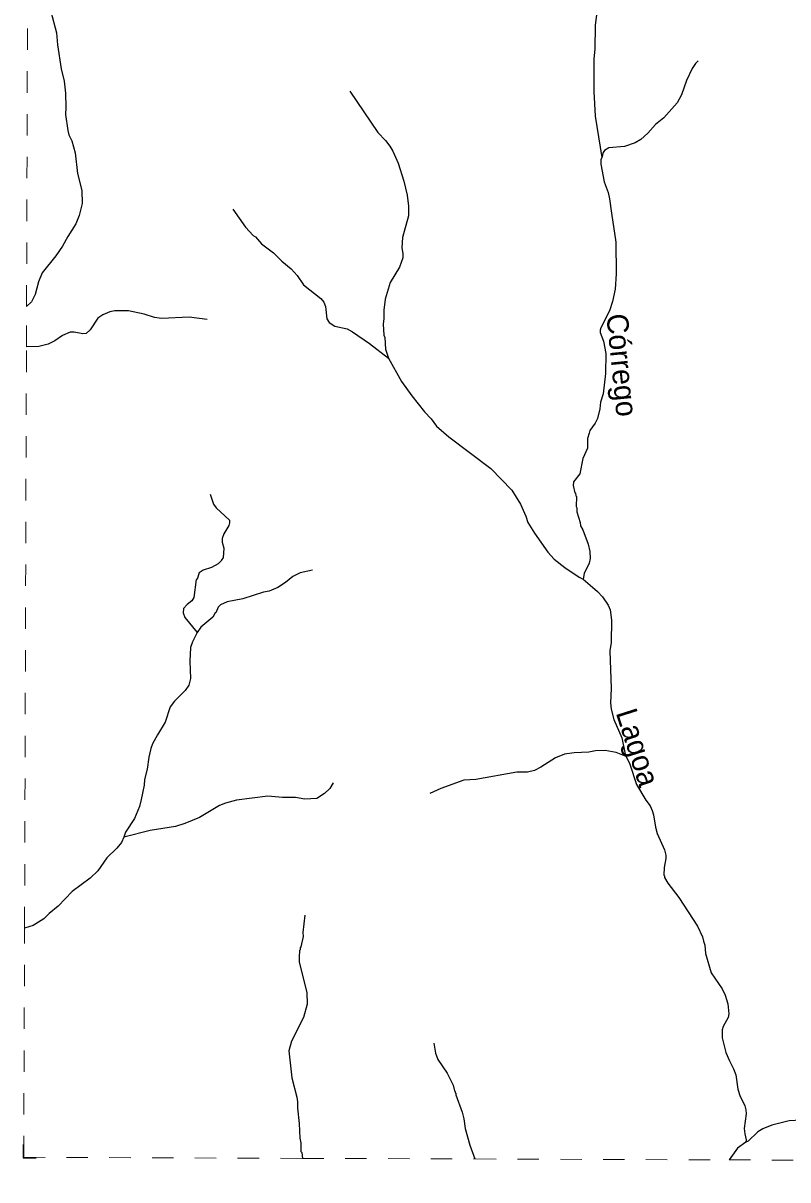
# Model space of a CAD drawing. Extents: x 551.6 to 577.6, y 7567 to 7594.7.
# Drawn here: x 551.61 to 555.19, y 7566.95 to 7572.36 of the extents above; entities that cross this region are included whole.
import ezdxf
from ezdxf.enums import TextEntityAlignment as Align

# ---------------------------------------------------------------- set-up
doc = ezdxf.new("R2010")
doc.units = 0
doc.header["$LTSCALE"] = 0.04
doc.linetypes.add('SHORT_DASHED', pattern=[2.7, 1.5, -1.2])
for name, color, linetype, lineweight in [('53', 7, 'SHORT_DASHED', 13), ('63', 7, 'Continuous', 25), ('7', 7, 'Continuous', 25)]:
    doc.layers.add(name, color=color, linetype=linetype, lineweight=lineweight)
doc.layers.add('61', color=7, linetype='Continuous')

msp = doc.modelspace()

# ---------------------------------------------------------------- linework, layer by layer
at = {"layer": '53'}
for points in [[(551.613, 7567.0572), (551.6165, 7568.1281), (551.6253, 7570.846), (551.6259, 7571.0339), (551.6348, 7573.7652), (551.6406, 7575.5319), (551.6443, 7576.6663), (551.6448, 7576.8423), (551.646, 7577.1998), (551.6475, 7577.6707), (551.6503, 7578.541), (551.6589, 7581.176)], [(551.613, 7567.0572), (552.9162, 7567.0524), (553.7221, 7567.0495), (554.9107, 7567.0451), (556.1477, 7567.0406), (557.2075, 7567.0367), (559.4055, 7567.0287), (559.6981, 7567.0276), (560.556, 7567.0244), (562.9715, 7567.0156), (564.6334, 7567.0092), (566.4358, 7567.0011), (566.7714, 7566.9996), (570.8595, 7566.9812), (572.5416, 7566.9737), (572.8363, 7566.9724), (573.5039, 7566.9694), (573.609, 7566.9689), (574.6855, 7566.9641), (575.0536, 7566.9624), (576.5544, 7566.9557), (577.1266, 7566.9531), (577.4204, 7566.9518)]]:
    msp.add_lwpolyline(points, dxfattribs=at)
at = {"layer": '63'}
msp.add_lwpolyline([(551.6099, 7567.1168), (551.6099, 7567.0552), (551.6706, 7567.0552)], dxfattribs=at)
at = {"layer": '7'}
for points in [[(551.7261, 7572.9167), (551.7245, 7572.8515), (551.7213, 7572.8403), (551.7229, 7572.7727), (551.7358, 7572.697), (551.739, 7572.693), (551.7406, 7572.6391), (551.7567, 7572.5473), (551.7583, 7572.5023), (551.739, 7572.4129), (551.7663, 7572.3139), (551.7704, 7572.2576), (551.7873, 7572.1449), (551.8017, 7572.087), (551.8082, 7572.0322), (551.809, 7571.9646)], [(554.3071, 7572.4628), (554.2894, 7572.3864), (554.2846, 7572.3477), (554.2837, 7572.2367), (554.2789, 7572.1916), (554.2789, 7572.0387), (554.2854, 7571.9244), (554.3154, 7571.7308)], [(554.7658, 7572.1827), (554.7537, 7572.1707), (554.7377, 7572.1465), (554.7119, 7572.0902), (554.6878, 7572.0234), (554.6676, 7571.9864), (554.6057, 7571.9163), (554.5662, 7571.8858), (554.5316, 7571.8447), (554.4986, 7571.8149), (554.4721, 7571.7996), (554.4222, 7571.7827), (554.3481, 7571.7763), (554.3288, 7571.7642), (554.3224, 7571.7538), (554.3154, 7571.7308)], [(553.1369, 7572.0411), (553.2689, 7571.8479), (553.3043, 7571.8101), (553.3244, 7571.7844), (553.3381, 7571.7602), (553.3631, 7571.7039), (553.3904, 7571.6202), (553.4057, 7571.555), (553.4113, 7571.5027), (553.4113, 7571.4576), (553.384, 7571.3562), (553.3808, 7571.3079), (553.3856, 7571.2822), (553.3856, 7571.262), (553.3695, 7571.2178), (553.326, 7571.147), (553.3027, 7571.0681), (553.2963, 7571.0166), (553.2971, 7570.978), (553.2938, 7570.9522), (553.2971, 7570.9007), (553.3011, 7570.8894)], [(551.809, 7571.9646), (551.8082, 7571.9325), (551.8194, 7571.8568), (551.8243, 7571.8375), (551.8372, 7571.8085), (551.8533, 7571.7522), (551.8645, 7571.6564), (551.8838, 7571.5767), (551.8854, 7571.5156), (551.8726, 7571.4592), (551.8565, 7571.4206), (551.8186, 7571.361), (551.7945, 7571.316), (551.7631, 7571.2709), (551.6987, 7571.192), (551.6818, 7571.1502), (551.6665, 7571.0906), (551.6488, 7571.0568), (551.6259, 7571.0339)], [(554.3154, 7571.7308), (554.3111, 7571.7208), (554.3111, 7571.6991), (554.3272, 7571.617), (554.3449, 7571.5671), (554.3513, 7571.5381), (554.361, 7571.4705)], [(552.5905, 7571.489), (552.65, 7571.4045), (552.6862, 7571.3667), (552.6967, 7571.3594), (552.7241, 7571.3272), (552.7804, 7571.2854), (552.819, 7571.2459), (552.8633, 7571.2105), (552.8906, 7571.1792), (552.9212, 7571.1357), (553.0017, 7571.0721), (553.0154, 7571.0544), (553.0242, 7571.0343), (553.0299, 7570.9764), (553.0403, 7570.9602), (553.0669, 7570.9425), (553.1249, 7570.9297), (553.1506, 7570.916), (553.2295, 7570.8621), (553.318, 7570.7929)], [(554.361, 7571.4705), (554.3819, 7571.3353), (554.3835, 7571.1872), (554.3787, 7571.1148), (554.3666, 7571.0584), (554.3513, 7571.0134), (554.3111, 7570.9345), (554.3079, 7570.9232), (554.3079, 7570.9136), (554.3232, 7570.8717), (554.3353, 7570.8154), (554.3336, 7570.722), (554.3216, 7570.6255), (554.3095, 7570.5868), (554.3063, 7570.5562), (554.2958, 7570.5112), (554.2854, 7570.4886), (554.2596, 7570.454), (554.2564, 7570.4428)], [(552.4705, 7570.9731), (552.386, 7570.9852), (552.2573, 7570.9779), (552.2235, 7570.9828), (552.1752, 7570.9981), (552.1028, 7571.0142), (552.0384, 7571.0142), (552.0158, 7571.0101), (551.982, 7570.9956), (551.9587, 7570.9804), (551.9241, 7570.9256), (551.9048, 7570.9079), (551.8887, 7570.9071), (551.8484, 7570.9144), (551.8291, 7570.9144), (551.7937, 7570.8991), (551.7583, 7570.8741), (551.7277, 7570.8588), (551.6827, 7570.8468), (551.6253, 7570.846)], [(553.3011, 7570.8894), (553.3051, 7570.8347), (553.318, 7570.7929)], [(553.318, 7570.7929), (553.3791, 7570.6834), (553.4274, 7570.6174), (553.487, 7570.5426), (553.5176, 7570.5095), (553.5425, 7570.4749), (553.6005, 7570.425), (553.7977, 7570.277), (553.895, 7570.1764), (553.9361, 7570.1104), (553.961, 7570.0541), (553.9699, 7570.0251), (554.0004, 7569.9752)], [(554.2564, 7570.4428), (554.2483, 7570.4178), (554.2483, 7570.3728), (554.2274, 7570.3245), (554.2129, 7570.252), (554.184, 7570.215), (554.1815, 7570.1973), (554.1904, 7570.1635), (554.1936, 7570.1619), (554.1944, 7570.1498), (554.1976, 7570.1466), (554.1952, 7570.0991), (554.1984, 7570.0927), (554.1984, 7570.075), (554.2145, 7570.0251), (554.2161, 7570.0098), (554.2274, 7569.9904), (554.2516, 7569.9237), (554.2604, 7569.8899), (554.2612, 7569.8561), (554.2564, 7569.8351), (554.2338, 7569.7869), (554.2282, 7569.7605), (554.2612, 7569.7321)], [(552.4842, 7570.1579), (552.5003, 7570.1104), (552.5132, 7570.0935), (552.5744, 7570.0363), (552.5744, 7570.0235), (552.5711, 7570.0106), (552.5478, 7569.972), (552.5414, 7569.9494), (552.5414, 7569.9333), (552.5486, 7569.9044), (552.5454, 7569.8593), (552.5373, 7569.8504), (552.5373, 7569.8464), (552.522, 7569.8319), (552.4907, 7569.8142), (552.452, 7569.8013), (552.4327, 7569.7901), (552.423, 7569.7603), (552.4198, 7569.7579), (552.4086, 7569.6742), (552.3981, 7569.6581), (552.3764, 7569.642), (552.3603, 7569.6227), (552.3587, 7569.6018), (552.3667, 7569.5808), (552.4239, 7569.5107)], [(554.0004, 7569.9752), (554.0632, 7569.8867), (554.0938, 7569.8529), (554.1429, 7569.8142), (554.2097, 7569.7691), (554.2282, 7569.7605)], [(552.9631, 7569.8021), (552.9059, 7569.7901), (552.8705, 7569.7716), (552.8367, 7569.7442), (552.8013, 7569.7208), (552.7611, 7569.7031), (552.7337, 7569.6983), (552.6371, 7569.6677), (552.5647, 7569.6541), (552.5325, 7569.6396), (552.5212, 7569.6291), (552.5116, 7569.6025), (552.5084, 7569.6017), (552.4971, 7569.5816), (552.4408, 7569.5358), (552.4239, 7569.5107)], [(554.2612, 7569.7321), (554.2958, 7569.7023), (554.3192, 7569.6774), (554.3449, 7569.638), (554.3546, 7569.6162), (554.3618, 7569.568), (554.3594, 7569.4633), (554.353, 7569.4247), (554.3594, 7569.2493), (554.3562, 7569.1816), (554.3594, 7569.1527), (554.3723, 7569.1044), (554.4093, 7569.0175), (554.4254, 7568.941), (554.4302, 7568.9305), (554.4463, 7568.8951)], [(552.4239, 7569.5107), (552.4013, 7569.4673), (552.3933, 7569.4408), (552.3892, 7569.3764)], [(552.3892, 7569.3764), (552.3925, 7569.2959), (552.3844, 7569.2637), (552.3683, 7569.2396), (552.3184, 7569.1889), (552.2975, 7569.1623), (552.2742, 7569.0915), (552.2379, 7569.032), (552.2154, 7568.9893), (552.2074, 7568.9676), (552.1977, 7568.9273), (552.1897, 7568.871), (552.1768, 7568.8227), (552.1752, 7568.797), (552.1615, 7568.7294), (552.1534, 7568.6972), (552.1309, 7568.6408)], [(554.4302, 7568.9305), (554.3836, 7568.949), (554.3321, 7568.9587), (554.287, 7568.9571), (554.2548, 7568.9515), (554.1872, 7568.9482), (554.1421, 7568.9418), (554.0987, 7568.9249), (554.0311, 7568.8814), (554.0005, 7568.8653), (553.9683, 7568.8581), (553.9184, 7568.8573), (553.7268, 7568.8235), (553.6705, 7568.8195), (553.5627, 7568.7816), (553.512, 7568.7575)], [(554.4463, 7568.8951), (554.4785, 7568.8002), (554.522, 7568.7261), (554.5413, 7568.6996), (554.5509, 7568.6778), (554.5574, 7568.6585), (554.567, 7568.6006), (554.5751, 7568.5716), (554.6097, 7568.4943), (554.6153, 7568.4702), (554.6153, 7568.4541), (554.6073, 7568.4123), (554.6057, 7568.3768), (554.6089, 7568.3736), (554.6089, 7568.3656), (554.625, 7568.3382), (554.6765, 7568.2722), (554.7634, 7568.1378), (554.7867, 7568.0871), (554.7908, 7568.0678)], [(553.0597, 7568.8081), (553.0436, 7568.7817), (553.0194, 7568.7575), (552.9832, 7568.7342), (552.9269, 7568.7318), (552.8834, 7568.739), (552.8222, 7568.739), (552.7546, 7568.7462), (552.6082, 7568.7269), (552.5567, 7568.7132), (552.5277, 7568.702), (552.4343, 7568.6456), (552.3667, 7568.6175), (552.3217, 7568.6038), (552.2042, 7568.5845), (552.0803, 7568.5545)], [(552.1309, 7568.6408), (552.0891, 7568.5764), (552.0803, 7568.5545)], [(552.0803, 7568.5545), (552.0697, 7568.5282), (552.048, 7568.5024), (552.0013, 7568.4565), (551.9595, 7568.3961), (551.9241, 7568.3615), (551.8396, 7568.2996), (551.7736, 7568.2312), (551.7309, 7568.1966), (551.7068, 7568.1716), (551.6569, 7568.1402), (551.6165, 7568.1281)], [(552.9269, 7568.1893), (552.9172, 7568.108), (552.9188, 7568.0887), (552.9091, 7568.0404), (552.9059, 7568.0372), (552.9059, 7568.0268), (552.9027, 7568.0235), (552.9003, 7567.9922), (552.9011, 7567.9696), (552.9373, 7567.828), (552.9381, 7567.7724), (552.9212, 7567.7105), (552.8649, 7567.5994), (552.852, 7567.5543), (552.8657, 7567.4288), (552.8898, 7567.3387), (552.8931, 7567.3161), (552.8931, 7567.2872), (552.9011, 7567.2147)], [(554.7908, 7568.0678), (554.7972, 7568.0485), (554.8012, 7568.0099), (554.827, 7567.9197), (554.8793, 7567.8441), (554.8922, 7567.8159), (554.9051, 7567.7749), (554.9099, 7567.7282), (554.9067, 7567.7105), (554.8841, 7567.6686), (554.8785, 7567.6525), (554.8793, 7567.6155), (554.8954, 7567.5479), (554.9123, 7567.5077), (554.9324, 7567.4714), (554.9421, 7567.4433), (554.9517, 7567.3757), (554.9606, 7567.3467), (554.9839, 7567.2984), (554.9888, 7567.2791), (554.9904, 7567.2598), (554.9823, 7567.1922)], [(553.5305, 7567.5906), (553.5385, 7567.5447), (553.5498, 7567.5141), (553.5924, 7567.4513), (553.6206, 7567.395), (553.627, 7567.3676), (553.6302, 7567.3644), (553.6302, 7567.358), (553.6335, 7567.3564), (553.6335, 7567.3499), (553.6624, 7567.2678), (553.6705, 7567.2373), (553.6769, 7567.1922), (553.6987, 7567.1133), (553.7221, 7567.0495)], [(555.3912, 7567.2851), (555.3751, 7567.2847), (555.3413, 7567.2743), (555.2825, 7567.2388), (555.2479, 7567.2316), (555.1916, 7567.2276), (555.1674, 7567.2211)], [(552.9011, 7567.2147), (552.9043, 7567.1471), (552.9091, 7567.1246), (552.9091, 7567.0843), (552.9124, 7567.0795), (552.9162, 7567.0524)], [(554.9823, 7567.1922), (554.9839, 7567.1664), (554.9904, 7567.139), (554.9894, 7567.1275)], [(555.1674, 7567.2211), (555.1111, 7567.2075), (555.0693, 7567.1906), (555.0451, 7567.1761), (555, 7567.1334), (554.9894, 7567.1275)], [(554.9894, 7567.1275), (554.9509, 7567.1004), (554.9107, 7567.0451)]]:
    msp.add_lwpolyline(points, dxfattribs=at)

# ---------------------------------------------------------------- texts
at = {"layer": '61'}
for s, rotation, p in [('Córrego', 275.749, (554.3611, 7570.7559)), ('Lagoa', 287.655, (554.4368, 7568.9585))]:
    msp.add_text(s, height=0.1, rotation=rotation, dxfattribs=at).set_placement(p, align=Align.CENTER)

doc.saveas('drawing.dxf')
